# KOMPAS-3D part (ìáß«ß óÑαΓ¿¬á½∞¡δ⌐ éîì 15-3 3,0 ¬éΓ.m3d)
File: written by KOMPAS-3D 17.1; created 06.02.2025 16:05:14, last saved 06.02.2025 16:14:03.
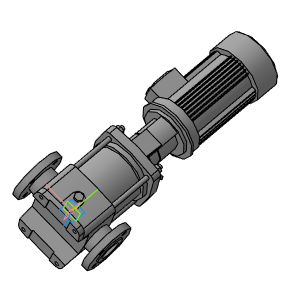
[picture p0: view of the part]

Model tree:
1. Операция без истории:1  (labels: Насос вертикальный ВМН 15-3 3,0 кВт)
